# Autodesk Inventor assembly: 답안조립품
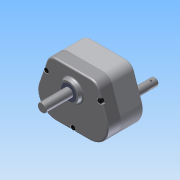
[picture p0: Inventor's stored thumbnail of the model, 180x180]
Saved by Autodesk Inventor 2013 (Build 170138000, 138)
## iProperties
Created: 2014-12
Part Number: 답안조립품
Document SubType Name: Assembly
Designer: Administrator
Author: Administrator
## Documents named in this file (14)
- C:\Users\Administrator\Desktop\441209V1030\답안조립품.iam
- C:\Users\Administrator\Desktop\441209V1030\본체.ipt
- C:\Users\Administrator\Desktop\441209V1030\베어링- 6203.ipt
- C:\Users\Administrator\Desktop\441209V1030\베어링- 6202.ipt
- C:\Users\Administrator\Desktop\441209V1030\커버.ipt
- C:\Users\Administrator\Desktop\441209V1030\메인축.ipt
- C:\Users\Administrator\Desktop\441209V1030\서브축.ipt
- C:\Users\Administrator\Desktop\441209V1030\키5x5.ipt
- C:\Users\Administrator\Desktop\441209V1030\메인기어.ipt
- C:\Users\Administrator\Desktop\441209V1030\서브기어.ipt
- C:\Users\Administrator\Desktop\441209V1030\멈춤링.ipt
- C:\Users\Administrator\Desktop\441209V1030\오일시일-D-15.ipt
- C:\Users\Administrator\Desktop\441209V1030\오일시일-D-17.ipt
- C:\Users\Administrator\Desktop\441209V1030\M 5 x 35.ipt
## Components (15 placed, 6 different names)
1. KS B 2023 6203 - 17 x 40 x 12:1
2. KS B 2023 6202 - 15 x 35 x 11:1
3. KS B 2023 6202 - 15 x 35 x 11:2
4. KS B 2023 6203 - 17 x 40 x 12:2
5. KS B 2023 6203 - 17 x 40 x 12:3
6. KS B 2023 6203 - 17 x 40 x 12:4
7. KS B 1336 17 x 1:1
8. KS B 1336 17 x 1:2
9. KS B 1336 17 x 1:3
10. KS B 2804 D D - 15 30 7:1
11. KS B 2804 D D - 15 30 7:2
12. KS B 2804 D D - 17 30 8:1
13. KS B 1003 - 미터 M 5 x 35:1
14. KS B 1003 - 미터 M 5 x 35:2
15. KS B 1003 - 미터 M 5 x 35:3
